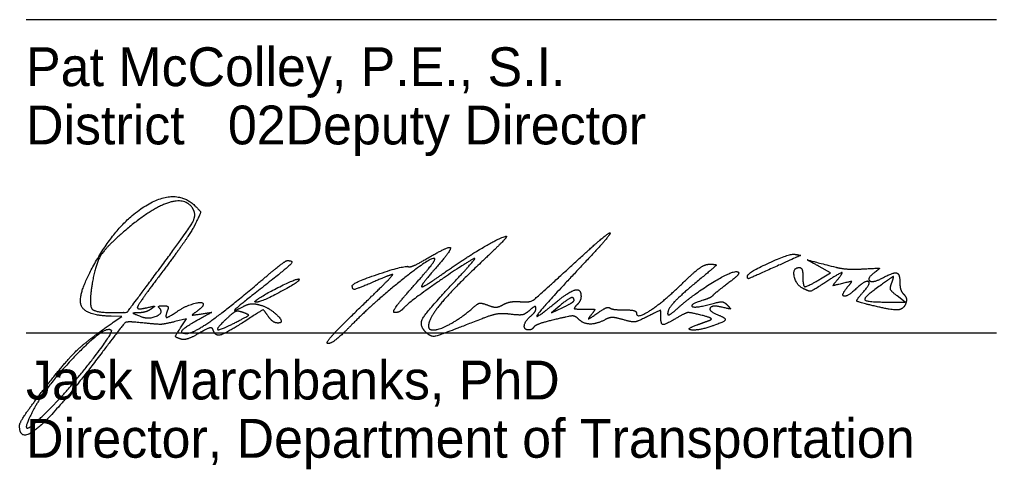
# Model space of a CAD drawing. Extents: x 0 to 34, y 0 to 22.
# Drawn here: x 24.504 to 28.028, y 7.305 to 8.926 of the extents above; entities that cross this region are included whole.
import ezdxf

# ---------------------------------------------------------------- set-up
doc = ezdxf.new("R2010")
doc.units = 0
doc.layers.add('SH_Data', color=7, linetype='Continuous')
doc.layers.add('SH_Text', color=7, linetype='Continuous')

msp = doc.modelspace()

# ---------------------------------------------------------------- linework, layer by layer
at = {"layer": 'SH_Data'}
for p, q in [((24.5279, 8.9262), (28.0279, 8.9262)), ((24.5279, 7.7968), (28.0279, 7.7968))]:
    msp.add_line(p, q, dxfattribs=at)
at = {"layer": 'SH_Text'}
for p, q in [((24.9902, 8.0019), (24.9902, 8.0019)), ((27.1295, 8.001), (27.1295, 8.001)), ((25.3555, 7.912), (25.3555, 7.912)), ((26.5045, 7.914), (26.5045, 7.914)), ((27.582, 7.8948), (27.582, 7.8948)), ((25.3107, 7.8703), (25.3107, 7.8703)), ((25.7273, 7.883), (25.7273, 7.883))]:
    msp.add_line(p, q, dxfattribs=at)
for points in [[(27.3933, 7.9914), (27.4297, 8.0129), (27.3889, 8.0359)], [(27.642, 7.9079), (27.6982, 7.908), (27.6695, 7.9301)], [(26.4527, 7.8943), (26.4232, 7.8687), (26.4638, 7.8884)], [(24.8425, 7.8349), (24.8732, 7.8561), (24.8354, 7.8568)], [(25.0855, 7.8151), (25.1067, 7.8474), (25.0649, 7.8373)]]:
    msp.add_lwpolyline(points, dxfattribs=at)
for points in [[(24.7789, 8.0526), (24.8651, 8.203), (25.0732, 8.319), (25.1389, 8.2534)], [(25.1299, 8.2442), (25.104, 8.2862), (24.9779, 8.245), (24.8825, 8.1634)], [(25.1389, 8.2534), (25.1577, 8.2346), (25.1577, 8.2295), (25.1394, 8.1911)], [(24.9902, 8.0019), (25.1115, 8.1653), (25.144, 8.2215), (25.1299, 8.2442)], [(25.1394, 8.1911), (25.1284, 8.1681), (25.0767, 8.0926), (25.0245, 8.0232)], [(24.8825, 8.1634), (24.8159, 8.1064), (24.7771, 8.0423), (24.766, 7.971)], [(26.0326, 8.0111), (26.1131, 8.0677), (26.2445, 8.1449), (26.2602, 8.1449)], [(26.2602, 8.1449), (26.265, 8.1449), (26.2237, 8.1023), (26.1684, 8.0502)], [(26.4869, 8.0315), (26.5619, 8.1006), (26.6279, 8.1572), (26.6336, 8.1573)], [(26.6336, 8.1573), (26.6394, 8.1574), (26.5873, 8.0972), (26.518, 8.0236)], [(25.9736, 8.0646), (26.0524, 8.1108), (26.0646, 8.0975), (26.0054, 8.0302)], [(27.1295, 8.001), (27.1295, 8.0134), (27.2823, 8.0837), (27.3012, 8.08)], [(27.3012, 8.08), (27.3219, 8.076), (27.3226, 8.0764), (27.201, 8.0218)], [(24.8354, 7.8568), (24.7375, 7.8585), (24.7141, 7.9396), (24.7789, 8.0526)], [(25.369, 7.9791), (25.4194, 8.022), (25.4649, 8.0571), (25.4701, 8.0573)], [(25.4701, 8.0573), (25.495, 8.0578), (25.4716, 8.0322), (25.3857, 7.9649)], [(25.7047, 7.9668), (25.7049, 7.9774), (25.8923, 8.0405), (25.908, 8.0354)], [(26.0017, 8.0644), (25.9921, 8.074), (25.7824, 7.907), (25.7045, 7.8278)], [(26.142, 8.0639), (26.0929, 8.0361), (25.9046, 7.9039), (25.8914, 7.888)], [(25.908, 8.0354), (25.9136, 8.0335), (25.9431, 8.0467), (25.9736, 8.0646)], [(25.9239, 7.964), (25.9702, 8.0157), (26.0052, 8.0609), (26.0017, 8.0644)], [(26.1684, 8.0502), (26.0687, 7.9565), (25.9795, 7.8484), (25.9795, 7.8214)], [(26.0768, 7.985), (26.123, 8.0342), (26.1523, 8.0697), (26.142, 8.0639)], [(26.8951, 7.9753), (26.9403, 8.019), (26.9774, 8.0447), (26.9951, 8.0444)], [(26.9951, 8.0444), (27.0194, 8.0439), (27.0156, 8.0375), (26.967, 7.9975)], [(27.3889, 8.0359), (27.3461, 8.06), (27.3452, 8.06), (27.4482, 8.0336)], [(27.4482, 8.0336), (27.4688, 8.0284), (27.5138, 8.0256), (27.5482, 8.0275)], [(24.844, 7.8699), (24.8907, 7.8699), (24.8953, 7.874), (24.9902, 8.0019)], [(25.0245, 8.0232), (24.9722, 7.9539), (24.9295, 7.8932), (24.9295, 7.8884)], [(25.7273, 7.883), (25.7983, 7.9514), (25.8537, 8.0074), (25.8502, 8.0074)], [(25.8502, 8.0074), (25.8468, 8.0074), (25.8178, 7.9962), (25.7857, 7.9824)], [(26.0054, 8.0302), (25.9774, 7.9984), (25.9545, 7.9687), (25.9545, 7.9643)], [(25.9545, 7.9643), (25.9545, 7.9598), (25.9896, 7.9809), (26.0326, 8.0111)], [(26.3119, 7.9091), (26.3453, 7.9063), (26.3688, 7.9227), (26.4869, 8.0315)], [(26.518, 8.0236), (26.3885, 7.8861), (26.3564, 7.8388), (26.4386, 7.9065)], [(26.8763, 7.8841), (26.93, 7.9329), (27.0769, 8.0229), (27.0938, 8.0172)], [(27.0938, 8.0172), (27.1022, 8.0144), (27.087, 7.9957), (27.0599, 7.9755)], [(27.201, 8.0218), (27.1385, 7.9937), (27.1295, 7.9911), (27.1295, 8.001)], [(27.3305, 7.9569), (27.304, 7.9711), (27.293, 8.0324), (27.317, 8.0324)], [(27.317, 8.0324), (27.3238, 8.0324), (27.3295, 8.0184), (27.3295, 8.0012)], [(27.3295, 8.0012), (27.3295, 7.9644), (27.3438, 7.9622), (27.3933, 7.9914)], [(27.4529, 7.9866), (27.4773, 8.0162), (27.4615, 8.0124), (27.4052, 7.9752)], [(27.5482, 8.0275), (27.6031, 8.0306), (27.608, 8.029), (27.5881, 8.0142)], [(27.5881, 8.0142), (27.5593, 7.9927), (27.5822, 7.9763), (27.6159, 7.9944)], [(27.6497, 7.9756), (27.6596, 8.0014), (27.6514, 7.9983), (27.5888, 7.9527)], [(27.6159, 7.9944), (27.6561, 8.0159), (27.6795, 8.0101), (27.6795, 7.9787)], [(24.766, 7.971), (24.7545, 7.8977), (24.776, 7.8699), (24.844, 7.8699)], [(25.1076, 7.7949), (25.1307, 7.7949), (25.2567, 7.8837), (25.369, 7.9791)], [(25.3857, 7.9649), (25.2925, 7.8919), (25.271, 7.8704), (25.315, 7.8939)], [(25.3555, 7.912), (25.3759, 7.9299), (25.5079, 7.9956), (25.5131, 7.9905)], [(25.5131, 7.9905), (25.5193, 7.9843), (25.3767, 7.9074), (25.359, 7.9074)], [(25.7857, 7.9824), (25.7231, 7.9556), (25.7044, 7.952), (25.7047, 7.9668)], [(25.8581, 7.8699), (25.8478, 7.8699), (25.8767, 7.9112), (25.9239, 7.964)], [(25.9697, 7.7993), (25.9445, 7.8246), (25.9734, 7.8747), (26.0768, 7.985)], [(26.7295, 7.8684), (26.7295, 7.8456), (26.8248, 7.907), (26.8951, 7.9753)], [(26.967, 7.9975), (26.8929, 7.9366), (26.842, 7.883), (26.842, 7.8663)], [(27.0599, 7.9755), (27.0328, 7.9553), (27.0079, 7.9353), (27.0045, 7.9311)], [(27.4052, 7.9752), (27.3652, 7.9487), (27.3519, 7.9454), (27.3305, 7.9569)], [(27.4723, 7.9749), (27.4392, 7.9667), (27.4374, 7.9678), (27.4529, 7.9866)], [(27.4924, 7.9642), (27.507, 7.9818), (27.5047, 7.983), (27.4723, 7.9749)], [(27.5211, 7.9554), (27.4892, 7.9255), (27.4661, 7.9325), (27.4924, 7.9642)], [(27.5462, 7.9428), (27.5767, 7.9764), (27.5551, 7.9874), (27.5211, 7.9554)], [(27.6695, 7.9301), (27.6491, 7.9458), (27.6434, 7.959), (27.6497, 7.9756)], [(27.6795, 7.9787), (27.6795, 7.9629), (27.6858, 7.9436), (27.6936, 7.9358)], [(26.4386, 7.9065), (26.487, 7.9464), (26.5295, 7.9568), (26.5295, 7.9287)], [(26.5295, 7.9287), (26.5295, 7.9198), (26.5227, 7.9057), (26.5145, 7.8974)], [(27.0045, 7.9311), (27.001, 7.9268), (26.9856, 7.9194), (26.9701, 7.9145)], [(27.582, 7.8948), (27.5272, 7.9077), (27.5215, 7.9154), (27.5462, 7.9428)], [(27.5888, 7.9527), (27.5461, 7.9217), (27.5626, 7.9078), (27.642, 7.9079)], [(27.6936, 7.9358), (27.7014, 7.928), (27.7044, 7.9128), (27.7003, 7.902)], [(24.9638, 7.8877), (24.9894, 7.8936), (24.9934, 7.8924), (24.9795, 7.883)], [(25.0086, 7.8867), (25.004, 7.8912), (25.0103, 7.8949), (25.0225, 7.8949)], [(25.0225, 7.8949), (25.037, 7.8949), (25.0422, 7.8885), (25.0375, 7.8762)], [(25.0736, 7.8743), (25.1025, 7.8941), (25.167, 7.9116), (25.167, 7.8997)], [(25.167, 7.8997), (25.167, 7.8952), (25.1572, 7.8843), (25.1453, 7.8756)], [(25.315, 7.8939), (25.3276, 7.9006), (25.3515, 7.9027), (25.3681, 7.8985)], [(25.359, 7.9074), (25.3542, 7.9074), (25.3526, 7.9095), (25.3555, 7.912)], [(25.3681, 7.8985), (25.4042, 7.8894), (25.4625, 7.8324), (25.4358, 7.8324)], [(26.137, 7.885), (26.1573, 7.903), (26.1701, 7.9056), (26.1939, 7.8966)], [(26.1939, 7.8966), (26.2141, 7.8889), (26.2329, 7.8896), (26.2489, 7.8987)], [(26.2489, 7.8987), (26.2623, 7.9062), (26.2906, 7.9109), (26.3119, 7.9091)], [(26.5045, 7.914), (26.5045, 7.9275), (26.4804, 7.9183), (26.4527, 7.8943)], [(26.4638, 7.8884), (26.4862, 7.8992), (26.5045, 7.9107), (26.5045, 7.914)], [(26.5145, 7.8974), (26.5028, 7.8858), (26.5087, 7.8824), (26.541, 7.8824)], [(26.9701, 7.9145), (26.9206, 7.8991), (26.9401, 7.8854), (26.9919, 7.8992)], [(26.9919, 7.8992), (27.0302, 7.9095), (27.0455, 7.9089), (27.0575, 7.8966)], [(27.0388, 7.8892), (27.0021, 7.8982), (26.9889, 7.8751), (27.0232, 7.862)], [(27.0575, 7.8966), (27.0702, 7.8837), (27.0666, 7.8823), (27.0388, 7.8892)], [(27.7003, 7.902), (27.6922, 7.8809), (27.651, 7.8784), (27.582, 7.8948)], [(24.9357, 7.8693), (24.9133, 7.8685), (24.9138, 7.8671), (24.9399, 7.8567)], [(24.9295, 7.8884), (24.9295, 7.8836), (24.9449, 7.8833), (24.9638, 7.8877)], [(24.9795, 7.883), (24.9692, 7.876), (24.9495, 7.8699), (24.9357, 7.8693)], [(24.9399, 7.8567), (24.9698, 7.8447), (25.026, 7.8693), (25.0086, 7.8867)], [(25.0375, 7.8762), (25.0285, 7.8529), (25.0414, 7.8523), (25.0736, 7.8743)], [(25.1453, 7.8756), (25.1264, 7.8618), (25.1284, 7.8605), (25.161, 7.8654)], [(25.161, 7.8654), (25.1977, 7.871), (25.1976, 7.8707), (25.1522, 7.8456)], [(25.3107, 7.8703), (25.2935, 7.8767), (25.277, 7.8716), (25.2576, 7.8538)], [(25.2826, 7.834), (25.329, 7.8577), (25.3325, 7.8623), (25.3107, 7.8703)], [(25.4011, 7.8571), (25.3843, 7.8812), (25.3822, 7.8807), (25.3165, 7.8384)], [(25.617, 7.7581), (25.6067, 7.7583), (25.6563, 7.8145), (25.7273, 7.883)], [(25.8914, 7.888), (25.8831, 7.878), (25.8682, 7.8699), (25.8581, 7.8699)], [(25.9975, 7.8074), (26.0192, 7.8074), (26.1006, 7.8527), (26.137, 7.885)], [(26.2749, 7.864), (26.2457, 7.8677), (26.2058, 7.8612), (26.1693, 7.8468)], [(26.3444, 7.8784), (26.3287, 7.8642), (26.3075, 7.8598), (26.2749, 7.864)], [(26.3412, 7.8074), (26.3229, 7.8074), (26.3274, 7.8402), (26.3482, 7.8574)], [(26.367, 7.8859), (26.367, 7.893), (26.3568, 7.8896), (26.3444, 7.8784)], [(26.3482, 7.8574), (26.3585, 7.866), (26.367, 7.8788), (26.367, 7.8859)], [(26.5199, 7.847), (26.5088, 7.8582), (26.4887, 7.8577), (26.4355, 7.8449)], [(26.541, 7.8824), (26.5785, 7.8824), (26.5809, 7.8804), (26.5654, 7.8611)], [(26.5654, 7.8611), (26.5533, 7.8461), (26.5598, 7.8478), (26.5871, 7.8669)], [(26.5871, 7.8669), (26.6085, 7.8819), (26.6293, 7.891), (26.6332, 7.8871)], [(26.6332, 7.8871), (26.6371, 7.8831), (26.6604, 7.8799), (26.6849, 7.8799)], [(26.6849, 7.8799), (26.7094, 7.8799), (26.7295, 7.8748), (26.7295, 7.8684)], [(26.817, 7.8559), (26.817, 7.8788), (26.8159, 7.8788), (26.7698, 7.8559)], [(26.842, 7.8663), (26.842, 7.8588), (26.8574, 7.8668), (26.8763, 7.8841)], [(26.9621, 7.8609), (26.9233, 7.8708), (26.9065, 7.8691), (26.8789, 7.8528)], [(26.992, 7.8417), (27.0034, 7.8458), (26.9917, 7.8533), (26.9621, 7.8609)], [(27.0232, 7.862), (27.0538, 7.8502), (27.0449, 7.8353), (26.9981, 7.8199)], [(24.5916, 7.5927), (24.6692, 7.6932), (24.7493, 7.7705), (24.8425, 7.8349)], [(24.9237, 7.835), (24.8903, 7.8383), (24.8786, 7.8278), (24.8019, 7.7262)], [(25.0649, 7.8373), (25.0246, 7.8276), (25.0023, 7.8272), (24.9237, 7.835)], [(25.1522, 7.8456), (25.1011, 7.8174), (25.0814, 7.7949), (25.1076, 7.7949)], [(25.3165, 7.8384), (25.2476, 7.794), (25.2101, 7.7843), (25.202, 7.8086)], [(25.2576, 7.8538), (25.2133, 7.8133), (25.2246, 7.8044), (25.2826, 7.834)], [(25.4358, 7.8324), (25.4262, 7.8324), (25.4106, 7.8435), (25.4011, 7.8571)], [(25.7045, 7.8278), (25.6667, 7.7893), (25.6273, 7.7579), (25.617, 7.7581)], [(26.1693, 7.8468), (26.0233, 7.7891), (25.9882, 7.7808), (25.9697, 7.7993)], [(26.4355, 7.8449), (26.3972, 7.8357), (26.3629, 7.8235), (26.3594, 7.8178)], [(26.6162, 7.8445), (26.5854, 7.8281), (26.5376, 7.8293), (26.5199, 7.847)], [(26.6807, 7.8446), (26.6538, 7.8523), (26.6307, 7.8523), (26.6162, 7.8445)], [(26.7698, 7.8559), (26.7324, 7.8374), (26.7138, 7.8351), (26.6807, 7.8446)], [(26.8789, 7.8528), (26.8339, 7.8262), (26.817, 7.8271), (26.817, 7.8559)], [(26.9981, 7.8199), (26.9515, 7.8045), (26.9042, 7.8102), (26.9482, 7.8259)], [(26.9482, 7.8259), (26.962, 7.8308), (26.9817, 7.8379), (26.992, 7.8417)], [(24.8354, 7.8057), (24.8145, 7.8266), (24.596, 7.6009), (24.5497, 7.5106)], [(24.6198, 7.5293), (24.6874, 7.5984), (24.8431, 7.798), (24.8354, 7.8057)], [(25.0843, 7.775), (25.0661, 7.782), (25.0662, 7.7856), (25.0855, 7.8151)], [(25.1508, 7.7948), (25.1252, 7.7797), (25.0953, 7.7708), (25.0843, 7.775)], [(25.202, 7.8086), (25.1991, 7.8172), (25.1799, 7.812), (25.1508, 7.7948)], [(25.9795, 7.8214), (25.9795, 7.8137), (25.9876, 7.8074), (25.9975, 7.8074)], [(26.3594, 7.8178), (26.3559, 7.8121), (26.3477, 7.8074), (26.3412, 7.8074)], [(24.8019, 7.7262), (24.6496, 7.5241), (24.5045, 7.3955), (24.5045, 7.4625)], [(24.5045, 7.4625), (24.5045, 7.4721), (24.5437, 7.5307), (24.5916, 7.5927)], [(24.5497, 7.5106), (24.5184, 7.4496), (24.55, 7.4581), (24.6198, 7.5293)]]:
    msp.add_open_spline(points, degree=2, dxfattribs=at)

# ---------------------------------------------------------------- texts
for s, p in [('Pat McColley, P.E., S.I.', (24.5279, 8.6862)), ('District       Deputy Director', (24.5279, 8.4762)), ('              02', (24.5279, 8.4762)), ('Jack Marchbanks, PhD', (24.5279, 7.5568)), ('Director, Department of Transportation', (24.5279, 7.3468))]:
    msp.add_text(s, height=0.14, dxfattribs=at).set_placement(p)

doc.saveas('drawing.dxf')
